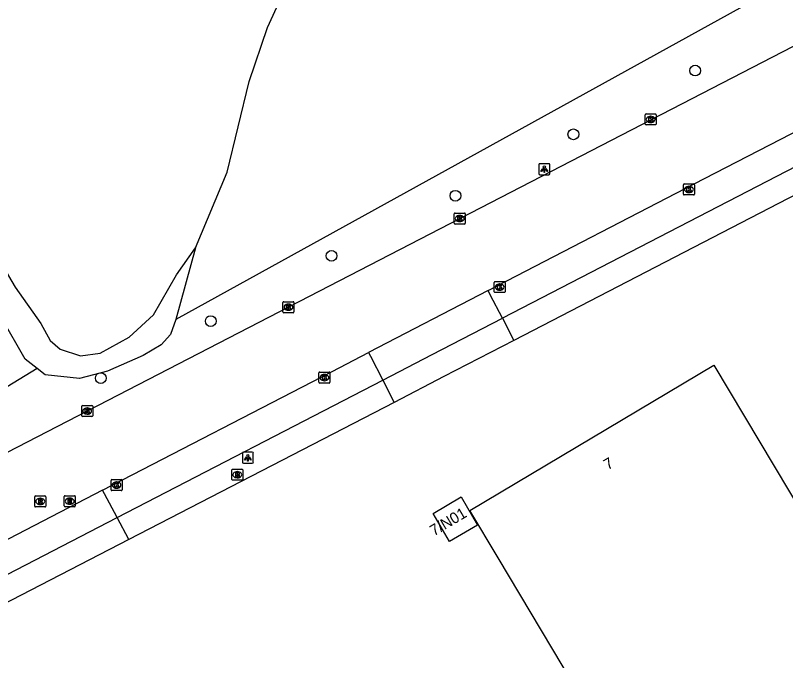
# Model space of a CAD drawing. Extents: x 156651 to 158072, y 387631 to 388990.
# Drawn here: x 157522.9 to 157592.7, y 388572.6 to 388631.1 of the extents above; entities that cross this region are included whole.
import ezdxf

# ---------------------------------------------------------------- set-up
doc = ezdxf.new("R2010")
doc.units = 0
for name, color, linetype in [('IMGEO_Boom', 7, 'Continuous'), ('IMGEO_Brandkraan', 7, 'Continuous'), ('IMGEO_Groenvoorziening', 7, 'Continuous'), ('IMGEO_Kolk', 7, 'Continuous'), ('IMGEO_Lichtpunt', 7, 'Continuous'), ('IMGEO_Loofbos', 7, 'Continuous'), ('IMGEO_Pand', 7, 'Continuous'), ('IMGEO_Pand_nummerreeks', 7, 'Continuous'), ('IMGEO_Parkeervlak_open', 7, 'Continuous'), ('IMGEO_Rijbaan_lokaal_gesloten', 7, 'Continuous'), ('IMGEO_Rioolput', 7, 'Continuous'), ('IMGEO_Voetpad_open', 7, 'Continuous')]:
    doc.layers.add(name, color=color, linetype=linetype)

msp = doc.modelspace()

# ---------------------------------------------------------------- linework, layer by layer
at = {"layer": 'IMGEO_Boom'}
for centre in [(157584.518, 388626.127), (157573.471, 388620.35), (157562.77, 388614.783), (157551.535, 388609.334), (157540.58, 388603.413), (157530.607, 388598.247)]:
    msp.add_circle(centre, 0.489, dxfattribs=at)
at = {"layer": 'IMGEO_Brandkraan'}
for p, q in [((157542.484, 388589.067), (157542.484, 388589.919)), ((157542.559, 388589.993), (157543.411, 388589.993)), ((157542.972, 388589.773), (157542.997, 388589.773)), ((157543.485, 388589.919), (157543.485, 388589.067)), ((157543.411, 388588.993), (157542.559, 388588.993)), ((157542.995, 388589.213), (157542.97, 388589.213))]:
    msp.add_line(p, q, dxfattribs=at)
for points in [[(157542.484, 388589.067), (157542.484, 388589.919)], [(157542.559, 388589.993), (157543.411, 388589.993)], [(157542.832, 388589.693), (157542.832, 388589.293), (157543.045, 388589.293)], [(157543.063, 388589.693), (157542.832, 388589.693)], [(157543.011, 388589.612), (157542.957, 388589.612), (157542.957, 388589.536)], [(157542.957, 388589.536), (157543.01, 388589.536)], [(157543.019, 388589.46), (157542.957, 388589.46), (157542.957, 388589.379)], [(157543.485, 388589.919), (157543.485, 388589.067)], [(157543.411, 388588.993), (157542.559, 388588.993)], [(157542.957, 388589.379), (157543.019, 388589.379)]]:
    msp.add_lwpolyline(points, dxfattribs=at)
for centre, radius, start, end in [((157542.561, 388589.917), 0.0765, 91.55205, 178.44795), ((157542.561, 388589.917), 0.0765, 91.55205, 178.44795), ((157543.012, 388589.574), 0.0379, 267.82845, 90.93552), ((157543.02, 388589.419), 0.0404, 269.87594, 90.50774), ((157543.067, 388589.548), 0.145, 59.4692, 91.53667), ((157543.092, 388589.595), 0.0922, 285.51372, 58.15012), ((157543.097, 388589.403), 0.105, 301.31148, 78.98903), ((157543.409, 388589.917), 0.0765, 1.55205, 88.44795), ((157543.409, 388589.917), 0.0765, 1.55205, 88.44795), ((157542.561, 388589.069), 0.0765, 181.55205, 268.44795), ((157542.561, 388589.069), 0.0765, 181.55205, 268.44795), ((157543.051, 388589.544), 0.251, 268.66757, 293.53466), ((157543.409, 388589.069), 0.0765, 271.55205, 358.44795), ((157543.409, 388589.069), 0.0765, 271.55205, 358.44795)]:
    msp.add_arc(centre, radius, start, end, dxfattribs=at)
for centre, major_axis, ratio, start_param, end_param in [((157542.971, 388589.493), (-0.387, 0.002), 0.722429, 4.712389, 7.853982), ((157542.996, 388589.493), (-0.39, 0.002), 0.717154, 1.570796, 4.712389)]:
    msp.add_ellipse(centre, major_axis=major_axis, ratio=ratio, start_param=start_param, end_param=end_param, dxfattribs=at)
at = {"layer": 'IMGEO_Groenvoorziening'}
for points in [[(157673.726, 388668.041), (157670.98, 388669.045), (157663.857, 388670.063), (157657.977, 388668.537), (157609.481, 388643.37), (157537.398, 388603.555)], [(157539.19, 388610.071), (157537.398, 388603.555)], [(157524.826, 388599.108), (157523.743, 388599.955), (157521.598, 388603.705)], [(157537.398, 388603.555), (157536.929, 388602.214), (157536.074, 388601.264), (157534.443, 388600.298), (157531.218, 388598.875), (157528.686, 388598.228), (157525.56, 388598.534), (157524.826, 388599.108)], [(157524.826, 388599.108), (157516.5, 388594.054)]]:
    msp.add_lwpolyline(points, dxfattribs=at)
at = {"layer": 'IMGEO_Kolk'}
for p, q in [((157579.984, 388621.278), (157579.984, 388622.13)), ((157580.059, 388622.204), (157580.911, 388622.204)), ((157580.472, 388621.984), (157580.497, 388621.984)), ((157580.985, 388622.13), (157580.985, 388621.278)), ((157580.911, 388621.204), (157580.059, 388621.204)), ((157580.495, 388621.424), (157580.47, 388621.424)), ((157583.449, 388614.93), (157583.449, 388615.782)), ((157583.524, 388615.856), (157584.376, 388615.856)), ((157583.937, 388615.636), (157583.962, 388615.636)), ((157584.45, 388615.782), (157584.45, 388614.93)), ((157584.376, 388614.856), (157583.524, 388614.856)), ((157583.96, 388615.076), (157583.935, 388615.076)), ((157562.736, 388613.213), (157563.588, 388613.213)), ((157562.661, 388612.287), (157562.661, 388613.139)), ((157563.149, 388612.993), (157563.174, 388612.993)), ((157563.662, 388613.139), (157563.662, 388612.287)), ((157563.588, 388612.213), (157562.736, 388612.213)), ((157563.172, 388612.433), (157563.147, 388612.433)), ((157566.281, 388606.079), (157566.281, 388606.931)), ((157566.356, 388607.005), (157567.208, 388607.005)), ((157567.282, 388606.931), (157567.282, 388606.079)), ((157566.792, 388606.225), (157566.767, 388606.225)), ((157566.769, 388606.785), (157566.794, 388606.785)), ((157567.208, 388606.005), (157566.356, 388606.005)), ((157547.126, 388604.25), (157547.126, 388605.102)), ((157547.201, 388605.176), (157548.053, 388605.176)), ((157547.614, 388604.956), (157547.639, 388604.956)), ((157548.127, 388605.102), (157548.127, 388604.25)), ((157548.053, 388604.176), (157547.201, 388604.176)), ((157547.637, 388604.396), (157547.612, 388604.396)), ((157550.392, 388597.87), (157550.392, 388598.722)), ((157550.467, 388598.796), (157551.319, 388598.796)), ((157550.88, 388598.576), (157550.905, 388598.576)), ((157551.393, 388598.722), (157551.393, 388597.87)), ((157551.319, 388597.796), (157550.467, 388597.796)), ((157550.903, 388598.016), (157550.878, 388598.016)), ((157528.872, 388594.839), (157528.872, 388595.691)), ((157528.947, 388595.765), (157529.799, 388595.765)), ((157529.873, 388595.691), (157529.873, 388594.839)), ((157529.36, 388595.545), (157529.385, 388595.545)), ((157529.799, 388594.765), (157528.947, 388594.765)), ((157529.383, 388594.985), (157529.358, 388594.985)), ((157531.533, 388588.126), (157531.533, 388588.978)), ((157531.608, 388589.052), (157532.46, 388589.052)), ((157532.021, 388588.832), (157532.046, 388588.832)), ((157532.534, 388588.978), (157532.534, 388588.126)), ((157532.46, 388588.052), (157531.608, 388588.052)), ((157532.044, 388588.272), (157532.019, 388588.272))]:
    msp.add_line(p, q, dxfattribs=at)
for points in [[(157579.984, 388621.278), (157579.984, 388622.13)], [(157580.059, 388622.204), (157580.911, 388622.204)], [(157580.305, 388621.904), (157580.428, 388621.904), (157580.428, 388621.753), (157580.558, 388621.904), (157580.722, 388621.904), (157580.576, 388621.753), (157580.729, 388621.504), (157580.577, 388621.504), (157580.492, 388621.668), (157580.428, 388621.601), (157580.428, 388621.504), (157580.305, 388621.504), (157580.305, 388621.904)], [(157580.985, 388622.13), (157580.985, 388621.278)], [(157580.911, 388621.204), (157580.059, 388621.204)], [(157583.449, 388614.93), (157583.449, 388615.782)], [(157583.524, 388615.856), (157584.376, 388615.856)], [(157583.77, 388615.556), (157583.893, 388615.556), (157583.893, 388615.405), (157584.023, 388615.556), (157584.187, 388615.556), (157584.041, 388615.405), (157584.194, 388615.156), (157584.042, 388615.156), (157583.957, 388615.32), (157583.893, 388615.253), (157583.893, 388615.156), (157583.77, 388615.156), (157583.77, 388615.556)], [(157584.45, 388615.782), (157584.45, 388614.93)], [(157584.376, 388614.856), (157583.524, 388614.856)], [(157562.736, 388613.213), (157563.588, 388613.213)], [(157562.661, 388612.287), (157562.661, 388613.139)], [(157562.982, 388612.913), (157563.105, 388612.913), (157563.105, 388612.762), (157563.235, 388612.913), (157563.399, 388612.913), (157563.253, 388612.762), (157563.406, 388612.513), (157563.254, 388612.513), (157563.169, 388612.677), (157563.105, 388612.61), (157563.105, 388612.513), (157562.982, 388612.513), (157562.982, 388612.913)], [(157563.662, 388613.139), (157563.662, 388612.287)], [(157563.588, 388612.213), (157562.736, 388612.213)], [(157566.281, 388606.079), (157566.281, 388606.931)], [(157566.356, 388607.005), (157567.208, 388607.005)], [(157567.282, 388606.931), (157567.282, 388606.079)], [(157566.602, 388606.705), (157566.725, 388606.705), (157566.725, 388606.554), (157566.855, 388606.705), (157567.019, 388606.705), (157566.873, 388606.554), (157567.026, 388606.305), (157566.874, 388606.305), (157566.789, 388606.469), (157566.725, 388606.402), (157566.725, 388606.305), (157566.602, 388606.305), (157566.602, 388606.705)], [(157567.208, 388606.005), (157566.356, 388606.005)], [(157547.126, 388604.25), (157547.126, 388605.102)], [(157547.201, 388605.176), (157548.053, 388605.176)], [(157547.447, 388604.876), (157547.57, 388604.876), (157547.57, 388604.725), (157547.7, 388604.876), (157547.864, 388604.876), (157547.718, 388604.725), (157547.871, 388604.476), (157547.719, 388604.476), (157547.634, 388604.64), (157547.57, 388604.573), (157547.57, 388604.476), (157547.447, 388604.476), (157547.447, 388604.876)], [(157548.127, 388605.102), (157548.127, 388604.25)], [(157548.053, 388604.176), (157547.201, 388604.176)], [(157550.392, 388597.87), (157550.392, 388598.722)], [(157550.467, 388598.796), (157551.319, 388598.796)], [(157550.713, 388598.496), (157550.836, 388598.496), (157550.836, 388598.345), (157550.966, 388598.496), (157551.13, 388598.496), (157550.984, 388598.345), (157551.137, 388598.096), (157550.985, 388598.096), (157550.9, 388598.26), (157550.836, 388598.193), (157550.836, 388598.096), (157550.713, 388598.096), (157550.713, 388598.496)], [(157551.393, 388598.722), (157551.393, 388597.87)], [(157551.319, 388597.796), (157550.467, 388597.796)], [(157528.872, 388594.839), (157528.872, 388595.691)], [(157528.947, 388595.765), (157529.799, 388595.765)], [(157529.873, 388595.691), (157529.873, 388594.839)], [(157529.193, 388595.465), (157529.316, 388595.465), (157529.316, 388595.314), (157529.446, 388595.465), (157529.61, 388595.465), (157529.464, 388595.314), (157529.617, 388595.065), (157529.465, 388595.065), (157529.38, 388595.229), (157529.316, 388595.162), (157529.316, 388595.065), (157529.193, 388595.065), (157529.193, 388595.465)], [(157529.799, 388594.765), (157528.947, 388594.765)], [(157531.533, 388588.126), (157531.533, 388588.978)], [(157531.608, 388589.052), (157532.46, 388589.052)], [(157531.854, 388588.752), (157531.977, 388588.752), (157531.977, 388588.601), (157532.107, 388588.752), (157532.271, 388588.752), (157532.125, 388588.601), (157532.278, 388588.352), (157532.126, 388588.352), (157532.041, 388588.516), (157531.977, 388588.449), (157531.977, 388588.352), (157531.854, 388588.352), (157531.854, 388588.752)], [(157532.534, 388588.978), (157532.534, 388588.126)], [(157532.46, 388588.052), (157531.608, 388588.052)]]:
    msp.add_lwpolyline(points, dxfattribs=at)
for centre, start, end in [((157580.061, 388622.128), 91.55205, 178.44795), ((157580.061, 388622.128), 91.55205, 178.44795), ((157580.909, 388622.128), 1.55205, 88.44795), ((157580.909, 388622.128), 1.55205, 88.44795), ((157580.061, 388621.28), 181.55205, 268.44795), ((157580.061, 388621.28), 181.55205, 268.44795), ((157580.909, 388621.28), 271.55205, 358.44795), ((157580.909, 388621.28), 271.55205, 358.44795), ((157583.526, 388615.78), 91.55205, 178.44795), ((157583.526, 388615.78), 91.55205, 178.44795), ((157584.374, 388615.78), 1.55205, 88.44795), ((157584.374, 388615.78), 1.55205, 88.44795), ((157583.526, 388614.932), 181.55205, 268.44795), ((157583.526, 388614.932), 181.55205, 268.44795), ((157584.374, 388614.932), 271.55205, 358.44795), ((157584.374, 388614.932), 271.55205, 358.44795), ((157562.738, 388613.137), 91.55205, 178.44795), ((157562.738, 388613.137), 91.55205, 178.44795), ((157563.586, 388613.137), 1.55205, 88.44795), ((157563.586, 388613.137), 1.55205, 88.44795), ((157562.738, 388612.289), 181.55205, 268.44795), ((157562.738, 388612.289), 181.55205, 268.44795), ((157563.586, 388612.289), 271.55205, 358.44795), ((157563.586, 388612.289), 271.55205, 358.44795), ((157566.358, 388606.929), 91.55205, 178.44795), ((157566.358, 388606.929), 91.55205, 178.44795), ((157567.206, 388606.929), 1.55205, 88.44795), ((157567.206, 388606.929), 1.55205, 88.44795), ((157566.358, 388606.081), 181.55205, 268.44795), ((157566.358, 388606.081), 181.55205, 268.44795), ((157567.206, 388606.081), 271.55205, 358.44795), ((157567.206, 388606.081), 271.55205, 358.44795), ((157547.203, 388605.1), 91.55205, 178.44795), ((157547.203, 388605.1), 91.55205, 178.44795), ((157548.051, 388605.1), 1.55205, 88.44795), ((157548.051, 388605.1), 1.55205, 88.44795), ((157547.203, 388604.252), 181.55205, 268.44795), ((157547.203, 388604.252), 181.55205, 268.44795), ((157548.051, 388604.252), 271.55205, 358.44795), ((157548.051, 388604.252), 271.55205, 358.44795), ((157550.469, 388598.72), 91.55205, 178.44795), ((157550.469, 388598.72), 91.55205, 178.44795), ((157551.317, 388598.72), 1.55205, 88.44795), ((157551.317, 388598.72), 1.55205, 88.44795), ((157550.469, 388597.872), 181.55205, 268.44795), ((157550.469, 388597.872), 181.55205, 268.44795), ((157551.317, 388597.872), 271.55205, 358.44795), ((157551.317, 388597.872), 271.55205, 358.44795), ((157528.949, 388595.689), 91.55205, 178.44795), ((157528.949, 388595.689), 91.55205, 178.44795), ((157529.797, 388595.689), 1.55205, 88.44795), ((157529.797, 388595.689), 1.55205, 88.44795), ((157528.949, 388594.841), 181.55205, 268.44795), ((157528.949, 388594.841), 181.55205, 268.44795), ((157529.797, 388594.841), 271.55205, 358.44795), ((157529.797, 388594.841), 271.55205, 358.44795), ((157531.61, 388588.976), 91.55205, 178.44795), ((157531.61, 388588.976), 91.55205, 178.44795), ((157532.458, 388588.976), 1.55205, 88.44795), ((157532.458, 388588.976), 1.55205, 88.44795), ((157531.61, 388588.128), 181.55205, 268.44795), ((157531.61, 388588.128), 181.55205, 268.44795), ((157532.458, 388588.128), 271.55205, 358.44795), ((157532.458, 388588.128), 271.55205, 358.44795)]:
    msp.add_arc(centre, 0.0765, start, end, dxfattribs=at)
for centre, major_axis, ratio, start_param, end_param in [((157580.471, 388621.704), (-0.387, 0.002), 0.722429, 4.712389, 7.853982), ((157580.496, 388621.704), (-0.39, 0.002), 0.717154, 1.570796, 4.712389), ((157583.936, 388615.356), (-0.387, 0.002), 0.722429, 4.712389, 7.853982), ((157583.961, 388615.356), (-0.39, 0.002), 0.717154, 1.570796, 4.712389), ((157563.148, 388612.713), (-0.387, 0.002), 0.722429, 4.712389, 7.853982), ((157563.173, 388612.713), (-0.39, 0.002), 0.717154, 1.570796, 4.712389), ((157566.768, 388606.505), (-0.387, 0.002), 0.722429, 4.712389, 7.853982), ((157566.793, 388606.505), (-0.39, 0.002), 0.717154, 1.570796, 4.712389), ((157547.613, 388604.676), (-0.387, 0.002), 0.722429, 4.712389, 7.853982), ((157547.638, 388604.676), (-0.39, 0.002), 0.717154, 1.570796, 4.712389), ((157550.879, 388598.296), (-0.387, 0.002), 0.722429, 4.712389, 7.853982), ((157550.904, 388598.296), (-0.39, 0.002), 0.717154, 1.570796, 4.712389), ((157529.359, 388595.265), (-0.387, 0.002), 0.722429, 4.712389, 7.853982), ((157529.384, 388595.265), (-0.39, 0.002), 0.717154, 1.570796, 4.712389), ((157532.02, 388588.552), (-0.387, 0.002), 0.722429, 4.712389, 7.853982), ((157532.045, 388588.552), (-0.39, 0.002), 0.717154, 1.570796, 4.712389)]:
    msp.add_ellipse(centre, major_axis=major_axis, ratio=ratio, start_param=start_param, end_param=end_param, dxfattribs=at)
at = {"layer": 'IMGEO_Lichtpunt'}
for p, q in [((157570.339, 388617.593), (157570.339, 388616.786)), ((157570.339, 388617.593), (157570.339, 388616.786)), ((157571.241, 388617.688), (157570.433, 388617.688)), ((157571.241, 388617.688), (157570.433, 388617.688)), ((157571.335, 388616.786), (157571.335, 388617.593)), ((157571.335, 388616.786), (157571.335, 388617.593)), ((157570.433, 388616.692), (157571.241, 388616.692)), ((157570.433, 388616.692), (157571.241, 388616.692)), ((157544.347, 388591.534), (157543.539, 388591.534)), ((157544.347, 388591.534), (157543.539, 388591.534)), ((157543.445, 388591.439), (157543.445, 388590.632)), ((157543.445, 388591.439), (157543.445, 388590.632)), ((157544.441, 388590.632), (157544.441, 388591.439)), ((157544.441, 388590.632), (157544.441, 388591.439)), ((157543.539, 388590.538), (157544.347, 388590.538)), ((157543.539, 388590.538), (157544.347, 388590.538))]:
    msp.add_line(p, q, dxfattribs=at)
for points in [[(157570.713, 388617.257), (157570.752, 388617.229), (157570.564, 388616.967), (157570.526, 388616.994), (157570.713, 388617.257)], [(157570.815, 388617.209), (157570.862, 388617.209), (157570.862, 388616.887), (157570.815, 388616.887), (157570.815, 388617.209)], [(157570.925, 388617.229), (157570.963, 388617.256), (157571.15, 388616.994), (157571.111, 388616.966), (157570.925, 388617.229)], [(157543.819, 388591.103), (157543.858, 388591.075), (157543.67, 388590.813), (157543.632, 388590.84), (157543.819, 388591.103)], [(157543.921, 388591.055), (157543.968, 388591.055), (157543.968, 388590.733), (157543.921, 388590.733), (157543.921, 388591.055)], [(157544.031, 388591.075), (157544.069, 388591.102), (157544.256, 388590.84), (157544.217, 388590.812), (157544.031, 388591.075)]]:
    msp.add_lwpolyline(points, dxfattribs=at)
for centre in [(157570.838, 388617.391), (157543.944, 388591.237)]:
    msp.add_circle(centre, 0.0994, dxfattribs=at)
for centre, start, end in [((157570.433, 388617.593), 90, 180), ((157570.433, 388617.593), 90, 180), ((157571.241, 388617.593), 0, 90), ((157571.241, 388617.593), 0, 90), ((157570.433, 388616.786), 180, 270), ((157570.433, 388616.786), 180, 270), ((157571.241, 388616.786), 270, 0), ((157571.241, 388616.786), 270, 360), ((157543.539, 388591.439), 90, 180), ((157543.539, 388591.439), 90, 180), ((157544.347, 388591.439), 0, 90), ((157544.347, 388591.439), 0, 90), ((157543.539, 388590.632), 180, 270), ((157543.539, 388590.632), 180, 270), ((157544.347, 388590.632), 270, 0), ((157544.347, 388590.632), 270, 360)]:
    msp.add_arc(centre, 0.0946, start, end, dxfattribs=at)
at = {"layer": 'IMGEO_Loofbos'}
for points in [[(157558.427, 388651.534), (157556.24, 388650.451), (157554.248, 388649.766), (157550.332, 388647.845), (157525.191, 388636.463), (157512.714, 388630.085), (157511.223, 388629.17), (157510.745, 388627.998), (157511.853, 388625.826), (157514.706, 388620.852), (157516.983, 388616.394), (157518.421, 388613.309), (157521.734, 388608.394), (157522.849, 388606.496), (157525.176, 388603.213), (157526.013, 388601.67), (157526.912, 388600.873), (157528.777, 388600.262), (157530.551, 388600.5), (157533.17, 388601.959), (157535.388, 388603.978), (157537.458, 388607.623), (157539.19, 388610.071)], [(157539.19, 388610.071), (157542.079, 388616.922), (157544.055, 388625.147), (157545.72, 388630.048), (157547.892, 388634.814), (157550.686, 388640.549), (157553.403, 388645.635), (157555.68, 388648.696), (157557.951, 388651.125), (157558.427, 388651.534)]]:
    msp.add_lwpolyline(points, dxfattribs=at)
at = {"layer": 'IMGEO_Pand'}
for points in [[(157566.652, 388581.958), (157564.089, 388586.251), (157586.207, 388599.432), (157601.327, 388574.137), (157616.479, 388583.151), (157606.543, 388599.828), (157603.779, 388604.468), (157608.702, 388607.878), (157608.776, 388607.772), (157615.62, 388612.53)], [(157618.081, 388611.249), (157618.103, 388607.546), (157618.24, 388607.627), (157618.44, 388607.289), (157617.923, 388606.985), (157619.916, 388603.646), (157620.942, 388601.928), (157631.052, 388584.992), (157625.55, 388581.708), (157621.684, 388579.4), (157643.791, 388542.399), (157626.432, 388532.048), (157627.89, 388529.611), (157605.779, 388516.389), (157566.652, 388581.958)], [(157560.744, 388585.988), (157563.293, 388587.479), (157564.788, 388584.923), (157562.239, 388583.432), (157560.744, 388585.988)]]:
    msp.add_lwpolyline(points, dxfattribs=at)
at = {"layer": 'IMGEO_Parkeervlak_open'}
for points in [[(157567.036, 388603.672), (157565.93, 388605.81), (157565.74, 388606.176)], [(157554.885, 388600.558), (157555.056, 388600.228), (157556.175, 388598.066)], [(157532.103, 388585.626), (157530.947, 388587.75), (157530.762, 388588.09)]]:
    msp.add_lwpolyline(points, dxfattribs=at)
at = {"layer": 'IMGEO_Rijbaan_lokaal_gesloten'}
for points in [[(157398.778, 388527.866), (157628.073, 388646.266), (157656.001, 388660.593), (157661.642, 388663.293), (157663.387, 388663.988), (157664.804, 388664.4), (157666.39, 388664.428), (157667.498, 388664.368), (157670.171, 388663.945), (157671.812, 388663.295), (157672.05, 388663.148)], [(157565.74, 388606.176), (157585.362, 388616.331), (157611.947, 388630.046)], [(157565.74, 388606.176), (157554.885, 388600.558)], [(157530.762, 388588.09), (157551.605, 388598.86), (157554.885, 388600.558)], [(157530.762, 388588.09), (157518.329, 388581.665)]]:
    msp.add_lwpolyline(points, dxfattribs=at)
at = {"layer": 'IMGEO_Rioolput'}
for p, q in [((157524.613, 388586.644), (157524.613, 388587.496)), ((157524.688, 388587.57), (157525.54, 388587.57)), ((157525.101, 388587.35), (157525.126, 388587.35)), ((157525.614, 388587.496), (157525.614, 388586.644)), ((157527.288, 388586.662), (157527.288, 388587.514)), ((157527.363, 388587.588), (157528.215, 388587.588)), ((157527.776, 388587.368), (157527.801, 388587.368)), ((157528.289, 388587.514), (157528.289, 388586.662)), ((157525.124, 388586.79), (157525.099, 388586.79)), ((157527.799, 388586.808), (157527.774, 388586.808)), ((157525.54, 388586.57), (157524.688, 388586.57)), ((157528.215, 388586.588), (157527.363, 388586.588))]:
    msp.add_line(p, q, dxfattribs=at)
for points in [[(157524.613, 388586.644), (157524.613, 388587.496)], [(157524.688, 388587.57), (157525.54, 388587.57)], [(157525.614, 388587.496), (157525.614, 388586.644)], [(157527.288, 388586.662), (157527.288, 388587.514)], [(157527.363, 388587.588), (157528.215, 388587.588)], [(157528.289, 388587.514), (157528.289, 388586.662)], [(157525.202, 388587.268), (157524.95, 388587.27), (157524.95, 388586.87)], [(157524.95, 388586.87), (157525.074, 388586.87), (157525.074, 388587.032), (157525.085, 388587.032)], [(157525.128, 388587.189), (157525.074, 388587.189), (157525.074, 388587.108)], [(157525.074, 388587.108), (157525.126, 388587.108)], [(157525.132, 388587.003), (157525.203, 388586.87), (157525.343, 388586.87), (157525.278, 388586.996)], [(157527.877, 388587.286), (157527.625, 388587.288), (157527.625, 388586.888)], [(157527.625, 388586.888), (157527.749, 388586.888), (157527.749, 388587.05), (157527.76, 388587.05)], [(157527.803, 388587.207), (157527.749, 388587.207), (157527.749, 388587.126)], [(157527.749, 388587.126), (157527.801, 388587.126)], [(157527.807, 388587.021), (157527.878, 388586.888), (157528.018, 388586.888), (157527.953, 388587.014)], [(157525.54, 388586.57), (157524.688, 388586.57)], [(157528.215, 388586.588), (157527.363, 388586.588)]]:
    msp.add_lwpolyline(points, dxfattribs=at)
for centre, radius, start, end in [((157524.69, 388587.494), 0.0765, 91.55205, 178.44795), ((157524.69, 388587.494), 0.0765, 91.55205, 178.44795), ((157525.538, 388587.494), 0.0765, 1.55205, 88.44795), ((157525.538, 388587.494), 0.0765, 1.55205, 88.44795), ((157527.365, 388587.512), 0.0765, 91.55205, 178.44795), ((157527.365, 388587.512), 0.0765, 91.55205, 178.44795), ((157528.213, 388587.512), 0.0765, 1.55205, 88.44795), ((157528.213, 388587.512), 0.0765, 1.55205, 88.44795), ((157524.69, 388586.646), 0.0765, 181.55205, 268.44795), ((157524.69, 388586.646), 0.0765, 181.55205, 268.44795), ((157525.084, 388586.979), 0.0533, 26.02933, 88.69889), ((157525.11, 388587.297), 0.19, 274.7715, 282.96867), ((157525.134, 388587.093), 0.0964, 77.00612, 93.18647), ((157525.148, 388587.15), 0.0378, 276.66336, 79.67722), ((157525.201, 388587.158), 0.109, 350.36119, 89.41601), ((157525.199, 388587.158), 0.112, 277.58423, 350.98172), ((157525.183, 388586.943), 0.108, 29.51342, 73.79051), ((157525.538, 388586.646), 0.0765, 271.55205, 358.44795), ((157525.538, 388586.646), 0.0765, 271.55205, 358.44795), ((157527.365, 388586.664), 0.0765, 181.55205, 268.44795), ((157527.365, 388586.664), 0.0765, 181.55205, 268.44795), ((157527.759, 388586.997), 0.0533, 26.02933, 88.69889), ((157527.785, 388587.315), 0.19, 274.7715, 282.96867), ((157527.809, 388587.111), 0.0964, 77.00612, 93.18647), ((157527.823, 388587.168), 0.0378, 276.66336, 79.67722), ((157527.876, 388587.176), 0.109, 350.36119, 89.41601), ((157527.874, 388587.176), 0.112, 277.58423, 350.98172), ((157527.858, 388586.961), 0.108, 29.51342, 73.79051), ((157528.213, 388586.664), 0.0765, 271.55205, 358.44795), ((157528.213, 388586.664), 0.0765, 271.55205, 358.44795)]:
    msp.add_arc(centre, radius, start, end, dxfattribs=at)
for centre, major_axis, ratio, start_param, end_param in [((157525.1, 388587.07), (-0.387, 0.002), 0.722429, 4.712389, 7.853982), ((157525.125, 388587.07), (-0.39, 0.002), 0.717154, 1.570796, 4.712389), ((157527.775, 388587.088), (-0.387, 0.002), 0.722429, 4.712389, 7.853982), ((157527.8, 388587.088), (-0.39, 0.002), 0.717154, 1.570796, 4.712389)]:
    msp.add_ellipse(centre, major_axis=major_axis, ratio=ratio, start_param=start_param, end_param=end_param, dxfattribs=at)
at = {"layer": 'IMGEO_Voetpad_open'}
for points in [[(157613.229, 388627.56), (157567.036, 388603.672)], [(157614.38, 388625.618), (157568.072, 388601.671)], [(157556.175, 388598.066), (157560.661, 388600.375), (157567.036, 388603.672)], [(157567.036, 388603.672), (157568.072, 388601.671)], [(157568.072, 388601.671), (157561.726, 388598.389), (157557.204, 388596.047)], [(157532.103, 388585.626), (157556.175, 388598.066)], [(157556.175, 388598.066), (157557.204, 388596.047)], [(157557.204, 388596.047), (157533.162, 388583.611)], [(157519.62, 388579.167), (157532.103, 388585.626)], [(157533.162, 388583.611), (157532.103, 388585.626)], [(157533.162, 388583.611), (157520.661, 388577.166)]]:
    msp.add_lwpolyline(points, dxfattribs=at)

# ---------------------------------------------------------------- texts
at = {"layer": 'IMGEO_Pand_nummerreeks'}
for s, rotation, p in [('7', 30.79075, (157576.591, 388589.883)), ('7/N01', 30.64529, (157560.823, 388583.901))]:
    msp.add_text(s, height=1, rotation=rotation, dxfattribs=at).set_placement(p)

doc.saveas('drawing.dxf')
